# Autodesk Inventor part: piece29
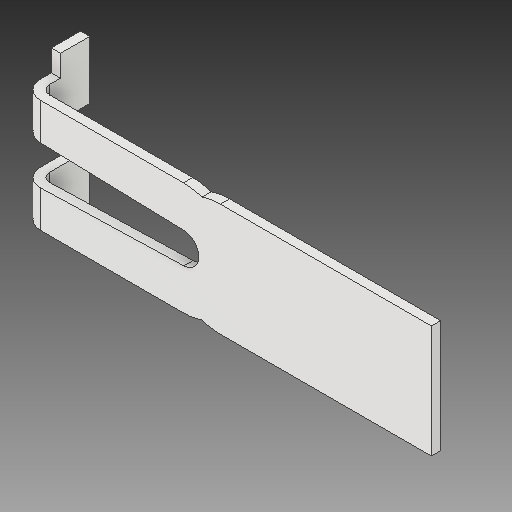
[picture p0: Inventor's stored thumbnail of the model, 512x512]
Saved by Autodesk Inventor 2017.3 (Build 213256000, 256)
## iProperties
Created: 2002-06
Part Number: piece29
Material: Générique
Document SubType Name: Modeling
Designer: ficho
Density: 1 g/cm^3
Appearance: Par défaut
Author: ficho
Sending System: SolidWorks 2009
Last Author: christophe
Last Saved: 2011-02-10
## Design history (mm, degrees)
feature "Enlèv. mat.-Extru.2"
node "Solide1"
